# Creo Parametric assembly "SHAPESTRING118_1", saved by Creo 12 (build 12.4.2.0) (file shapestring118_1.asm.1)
Units: Custom; MM, KILOGRAM, SECS

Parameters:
  PTC_WM_ITERATION = "0"
  PTC_WM_VERSION = "-.0"
  PTC_WM_LIFECYCLE_STATE = "In Work"
  PTC_WM_LIFECYCLE = "MO_CADDocument"
  PTC_WM_CREATED_BY = "Maximilian Roepper (Z0017RMS: MO)"
  PTC_WM_CREATED_ON = "18-Sep-26 11:36:42 AM"
  PTC_WM_MODIFIED_BY = "Maximilian Roepper (Z0017RMS: MO)"
  PTC_WM_MODIFIED_ON = "18-Sep-26 11:36:46 AM"
  PDMLINKNUMBER = "PDM000071455285"
  PTC_WM_NUMBER = "PDM000071455285"

Other parameters: WEIGHT, WEIGHT_FACTOR, WEIGHT_ADD, MC_ERRORS, SUPPLIER

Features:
  1. coordinate system
  2. imported feature
  3. component "SHAPESTRING069_1"
  4. component "SHAPESTRING115_1"
  5. component "SHAPESTRING116_1"
  6. component "SHAPESTRING117_1"

Other named items: DRW_VIEW_ORG, ROUGH-GROB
